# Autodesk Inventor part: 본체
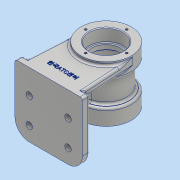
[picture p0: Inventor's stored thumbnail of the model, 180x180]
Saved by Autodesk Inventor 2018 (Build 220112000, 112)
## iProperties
Created: 2024-02
Part Number: 본체
Material: 알루미늄 6061
Document SubType Name: Modeling
Designer: home
Density: 2.7 g/cm^3
Appearance: 알루미늄 - 평지
Mass: 719.901 g
Surface Area: 647.209 cm^2
Volume: 266.63 cm^3
Author: home
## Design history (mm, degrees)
sketch "스케치2"
  geometry: L1 (-47, 45)-(47, 45); L2 (47, 45)-(47, -25); L3 (27, -45)-(-27, -45); L4 (-47, -25)-(-47, 45); L5 (-47, 45)-(47, -45); L6 (47, 45)-(-47, -45); A1 r 20 centre (27, -25) between (27, -45) and (47, -25); A2 r 20 centre (-27, -25) between (-47, -25) and (-27, -45); 1 further point
  constraints: 12 end point, 4 point on circle, 4 point on line, 4 tangent, 2 centre point, 2 midpoint, 2 parallel, 1 equal radius, 1 horizontal, 1 perpendicular
  dimensions: "d0" = 90 distance of L6.end L1.start; "d1" = 94 distance of L1.start L1.end; "d2" = 20 radius of A1
extrude "돌출1" new body sketch "스케치2" distance "d3" = 10; taper "d4" = 0 deg
sketch "스케치3"
  geometry: L1 (0, 0)-(70, 0); L2 (70, 0)-(70, 50); L3 (0, -45)-(-10, -45) reference; L4 (105, 50)-(94.5, 50); L5 (92.5, 32)-(90, 32); L6 (105, -28)-(94.5, -28); L7 (92.5, -10)-(90, -10); L8 (90.5, -4)-(90, -4); L9 (90.5, 26)-(90, 26); L10 (93.5, 49)-(93.5, 33); L11 (90, 32)-(90, 26); L12 (90, -4)-(90, -10); L13 (93.5, 23)-(93.5, -1); L14 (93.5, -11)-(93.5, -27); L15 (102, 28)-(98.5, 28); L16 (98.5, 28)-(98.5, -6); L17 (102, -6)-(98.5, -6); L18 (105, 50)-(105, 31); L19 (105, -9)-(105, -28); L20 (94.5, -28)-(93.5, -27); L21 (93.5, 49)-(94.5, 50); A1 r 3 centre (102, 31) between (102, 28) and (105, 31); A2 r 3 centre (102, -9) between (105, -9) and (102, -6); A3 r 1 centre (92.5, 33) between (92.5, 32) and (93.5, 33); A4 r 1 centre (92.5, -11) between (93.5, -11) and (92.5, -10); A5 r 3 centre (90.5, 23) between (93.5, 23) and (90.5, 26); A6 r 3 centre (90.5, -1) between (90.5, -4) and (93.5, -1); 4 further points
  constraints: 40 end point, 15 tangent, 12 point on circle, 10 perpendicular, 8 vertical, 6 centre point, 5 horizontal alignment, 4 horizontal, 4 point on line, 3 equal radius
  dimensions: "d5" = 70 distance of L1.start L1.end; "d9" = 95 distance from line of L2.end L3; "d10" = 18 distance between parallel lines of L5 L4; "d11" = 78 distance from line of L6.start L4; "d12" = 18 distance between parallel lines of L7 L6; "d13" = 6 distance between parallel lines of L9 L5; "d14" = 6 distance between parallel lines of L8 L7; "d15" = 22 distance between parallel lines of L15 L4; "d16" = 57 diameter of L16 L2; "d17" = 22 distance between parallel lines of L17 L6; "d18" = 3 radius of A1; "d19" = 1 radius of A3; "d20" = 3 radius of A5; "d21" = 1 distance of L6.end point (93.5, -28); "d22" = 1 distance of L14.end point (93.5, -28) (= d21); "d23" = 1 distance of L10.start point (93.5, 50) (= d21); "d24" = 1 distance of L4.end point (93.5, 50) (= d23); "d27" = 5 distance between parallel lines of L13 L16; "d31" = 15 distance from line of point (90, -28) L18; "d32" = 70 diameter of L18 L2; "d33" = 15 distance between parallel lines of L11 L18; "d34" = 15 distance between parallel lines of L12 L18; "d35" = 15 distance from line of point (90, 50) L18
revolve "회전1" sketch "스케치3" stored, may be unused: angle "d36" = 90 deg
sketch "스케치4"
  geometry: L1 (47, -45)-(-47, -45) reference; L2 (47, -45)-(47, -11); L3 (47, 25)-(47, -45) reference; L4 (47, -11)-(27, -11); L5 (47, -11)-(47, 25); L6 (47, 25)-(27, 25); C1 r 10 at (27, 25); C2 r 10 at (27, -11); 1 further point
  constraints: 8 end point, 2 centre point, 2 coincident, 2 horizontal, 2 point on line
  dimensions: "d37" = 34 distance of L1.start L2.end; "d38" = 20 distance of L2.end L4.end; "d39" = 36 distance of L5.end L2.end; "d40" = 20 distance of L5.end L6.end; "d41" = 20 diameter of C1; "d42" = 20 diameter of C2
extrude "돌출2" join sketch "스케치4" distance "d43" = 3; taper "d44" = 0 deg
fillet "모깎기1" dims "d45" = 3
sketch "스케치5"
  geometry: C1 r 10 at (0, 0) reference; C2 r 13 at (0, 0) reference; C3 r 13 at (0, -36) reference; C4 r 13 at (-54, 0) reference; C5 r 13 at (-54, -36) reference; 5 further points
  constraints: 4 coincident
hole "구멍1" sketch "스케치5" at (-54, 0), (0, 0), (0, -36), (-54, -36) diameter "d46" = 9; stored, may be unused: countersink angle "d50" = 90 deg, drill point angle "d52" = 118 deg; dims "d47" = 6, "d48" = 4, "d49" = 2, "d51" = 8
sketch "스케치6"
  geometry: L1 (0, -10)-(8, -10); L2 (0, -10)-(20, -10) reference; L3 (94, -10)-(0, -10) reference; L4 (94, -10)-(86, -10); L5 (8, -10)-(8, 0); L6 (8, 0)-(12.055, 71.969); L7 (86, -10)-(86, 0); L8 (94, 0)-(0, 0) reference; L9 (86, 0)-(81.945, 71.969); L10 (12.055, 71.969)-(26.283, 43.904); L11 (26.283, 43.904)-(48.752, 37.119); L12 (48.752, 37.119)-(69.663, 45.239); L13 (69.663, 45.239)-(77.598, 56.815); L14 (77.598, 56.815)-(81.945, 71.969); L15 (8, -10)-(86, -10); A1 r 35 centre (47, 70) between (12.055, 71.969) and (81.945, 71.969) reference; 1 further point
  constraints: 24 end point, 3 point on line, 2 point on circle, 2 tangent, 2 vertical, 1 horizontal
  dimensions: "d53" = 8 distance of L1.start L1.end; "d54" = 8 distance of L4.end L3.start; "d55" = 86.7748 deg angle of L8 L6; "d56" = 106.006 deg angle of L3 L14; "d57" = 55.5722 deg angle of L3 L13; "d58" = 21.2211 deg angle of L3 L12; "d59" = 16.8033 deg angle of L3 L11; "d60" = 63.1166 deg angle of L3 L10; "d61" = 45.65079 distance from line of L8.start L13; "d62" = 50.98071 distance from line of L8.start L12; "d63" = 22.45383 distance from line of L8.start L11
extrude "돌출3" join sketch "스케치6" distance "d64" = 10; taper "d65" = 0 deg
sketch "스케치8"
  geometry: L1 (0, -45)-(-10, -45) reference; L2 (0, -45)-(0, -33); L3 (0, -25)-(0, -45) reference; L4 (0, -33)-(42.502, -17.531); L5 (42.502, -17.531)-(42.502, 36.947); L6 (41.5, 28)-(41.5, -6) reference; L7 (42.502, 36.947)-(0, 36.947); L8 (0, 36.947)-(0, -33); 1 further point
  constraints: 10 end point, 2 perpendicular, 1 parallel, 1 point on line
  dimensions: "d66" = 12 distance of L1.start L2.end; "d67" = 70 deg angle of L8 L4; "d68" = 42.50207 distance between parallel lines of L8 L5; "d69" = 69.94666 distance from line of L2.end L7
extrude "돌출4" join sketch "스케치8" stored distance "d70" = 10; taper "d71" = 0 deg
fillet "모깎기3" dims "d73" = 3
fillet "모깎기4" dims "d74" = 3
fillet "모깎기5" dims "d75" = 3
fillet "모깎기6" dims "d76" = 3
fillet "모깎기9" dims "d79" = 3
fillet "모깎기10" dims "d80" = 3
fillet "모깎기11" dims "d81" = 3
fillet "모깎기12" dims "d82" = 3
fillet "모깎기13" dims "d83" = 3
fillet "모깎기14" dims "d84" = 3
sketch "스케치9"
  geometry: L1 (0, 0)-(0, 28.5); C1 r 35 at (0, 0) reference; A1 r 28.5 centre (0, 0) between (-7.238, -27.566) and (7.238, -27.566); A2 r 28.5 centre (0, 0) between (7.238, -27.566) and (-7.238, -27.566) reference; 2 further points
  constraints: 2 coincident, 2 end point, 1 centre point, 1 point on circle, 1 vertical
  dimensions: "d85" = 57 diameter of A1
hole "구멍2" sketch "스케치9" at (0, 28.5) diameter "d86" = 3.242; stored, may be unused: countersink angle "d90" = 90 deg, drill point angle "d92" = 118 deg; dims "d87" = 8, "d88" = 4, "d89" = 2, "d91" = 10
sketch "스케치10" dims "d96" = 57
  geometry: L1 (0, 0)-(0, 28.5); C1 r 35 at (0, 0) reference; 2 further points
  constraints: 2 coincident, 2 end point, 1 vertical, 1 vertical alignment, 2 other
hole "구멍3" sketch "스케치10" at (0, 28.5) diameter "d97" = 3.242; stored, may be unused: countersink angle "d101" = 90 deg, drill point angle "d103" = 118 deg; dims "d98" = 8, "d99" = 4, "d100" = 2, "d102" = 10
sketch "스케치11"
  geometry: L1 (88, 0)-(0, 0) reference; L2 (91, 0)-(91, 7) reference; 2 further points
  constraints: 1 other
  dimensions: "d107" = 20 distance from line of point (44, 20) L1; "d108" = 47 distance from line of point (44, 20) L2
feature "엠보싱1" sketch "스케치11" dims "d0" = 90, "d1" = 94, "d2" = 20, "d5" = 70, "d9" = 95, "d10" = 18, "d11" = 78, "d12" = 18, "d13" = 6, "d14" = 6, "d15" = 22, "d16" = 57, "d17" = 22, "d18" = 3, "d19" = 1, "d20" = 3, "d21" = 1, "d22" = 1 (= d21), "d23" = 1 (= d21), "d24" = 1 (= d23), "d27" = 5, "d31" = 15, "d32" = 70, "d33" = 15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
node "작업 평면1"
sketch "스케치12"
  geometry: L1 (-31.5, 28)-(31.5, 28) reference; L2 (-24.5, 50)-(24.5, 50) reference; L3 (0, 50)-(0, 11); C1 r 6 at (0, 11); 3 further points
  constraints: 2 end point, 1 centre point, 1 coincident, 1 midpoint, 1 vertical
  dimensions: "d112" = 39 distance of L3.start L3.end; "d113" = 12 diameter of C1
extrude "돌출5" join sketch "스케치12" stored distance "d114" = 10; taper "d115" = 0 deg
sketch "스케치13"
  geometry: C1 r 6 at (0, 0) reference; C2 r 3.5 at (0, 0); 2 further points
  constraints: 2 coincident, 1 centre point
  dimensions: "d116" = 7 diameter of C2
extrude "돌출6" cut sketch "스케치13" distance "d117" = 2; taper "d118" = 0 deg
sketch "스케치14"
  geometry: C1 r 3.5 at (0, 0) reference; C2 r 6 at (0, 0) reference; 2 further points
  constraints: 1 coincident
hole "구멍4" sketch "스케치14" at (0, 0) diameter "d119" = 5.188; stored, may be unused: countersink angle "d123" = 90 deg, drill point angle "d125" = 118 deg; dims "d120" = 12, "d121" = 4, "d122" = 2, "d124" = 16
fillet "모깎기15" dims "d126" = 3
node "솔리드1"
mirror "미러1"
pattern_circular "원형 패턴1" dims angle "d94" = 360 deg
pattern_circular "원형 패턴2" dims angle "d105" = 360 deg
node "투영된 루프1"
node "투영된 루프2"
other parameters: "d7" = 47, "d111" = -111.5
